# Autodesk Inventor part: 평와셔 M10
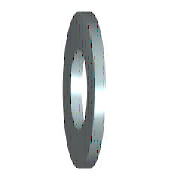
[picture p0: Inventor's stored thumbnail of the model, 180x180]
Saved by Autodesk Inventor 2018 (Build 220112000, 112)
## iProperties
IsCustomPart: 1
Created: 2012-02
Part Number: 평와셔 M10
Material: 스테인리스강
Description: 평면 와셔 - 일반 시리즈 - 제품 등급 A
Document SubType Name: Modeling
Standard: ISO 7089
Designer: mdu-01
Standard Revision: Second edition 2000-06-01
Standards Organization: ISO
Language: ko-KR
Size Designation: 10 - 140 HV
Categories: <MemberInstance><Categories><Category DisplayName="조임쇠" InternalName="e4da775c-781d-43d5-af7c-5136215cf5a6" Mnemonic="FSTN"><Category DisplayName="와셔" InternalN
Density: 8.08 g/cm^3
Appearance: 반광택
Author: mdu-01
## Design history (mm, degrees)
sketch "스케치"
  geometry: C1 r 10 at (0, 0); C2 r 5.25 at (0, 0); 1 further point
  constraints: 2 centre point, 2 coincident
  dimensions: "d0" = 10.5 diameter of C2 (= SD1); "d1" = 20 diameter of C1 (= SD2)
extrude "본체" new body sketch "스케치" distance "d2" = 2 (= SD); taper "d3" = 0 deg
workaxis "Work Axis1"
workplane "Work Plane1"
body "Solid1"
other parameters: "SD1" = 10.5 [user parameter; used in 1 equation term], "SD2" = 20 [user parameter; used in 1 equation term], "SD" = 2 [user parameter; used in 1 equation term], "d4" = 0, "d5" = 0, "d6" = 0, "d7" = 0
